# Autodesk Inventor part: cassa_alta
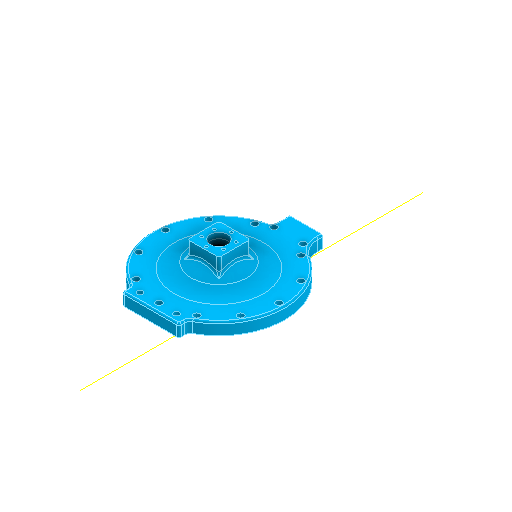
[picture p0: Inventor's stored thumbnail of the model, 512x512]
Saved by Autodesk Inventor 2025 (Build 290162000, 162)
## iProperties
Created: 2025-04
Part Number: cassa_alta
Material: Generico
Document SubType Name: Modeling
Designer: R5800u
Density: 1 g/cm^3
Appearance: Celeste medio
d120: -110,000 mm
d123: -125,000 mm
Author: R5800u
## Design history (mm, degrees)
sketch "Schizzo1"
  geometry: C1 r 80 at (0, 0); 1 further point
  constraints: 1 centre point, 1 coincident
  dimensions: "d0" = 160 diameter of C1
sketch "Schizzo2"
  geometry: L1 (0, -80)-(0, 80) reference; L2 (9, -75.641)-(-9, -75.641); A1 r 10 centre (0, -80) between (-9, -75.641) and (9, -75.641); 1 further point
  constraints: 2 end point, 2 point on circle, 1 centre point, 1 coincident, 1 horizontal
  dimensions: "d1" = 20 diameter of A1; "d11" = 18 distance of L2.end L2.start
node "Piano di lavoro1"
sketch "Schizzo3"
  geometry: L1 (0, -80)-(0, 80) reference; L2 (9, 64.412)-(-9, 64.412); A1 r 18 centre (0, 80) between (9, 64.412) and (-9, 64.412); 1 further point
  constraints: 2 end point, 2 point on circle, 1 centre point, 1 coincident, 1 perpendicular
  dimensions: "d3" = 36 diameter of A1; "d10" = 18 distance of L2.end L2.start
loft "Loft1" sketch "Schizzo3" dims "d4" = 0, "d5" = 90 deg, "d6" = 0, "d7" = 90 deg, "d8" = 0, "d9" = 90 deg
sketch "Schizzo4"
  geometry: A1 r 18 centre (0, 0) between (15.588, 9) and (15.588, -9) reference; 1 further point
sketch "Schizzo5"
  geometry: L1 (-4.359, -9)-(-4.359, 9) reference; A1 r 10 centre (0, 0) between (-4.359, -9) and (-4.359, 9) reference; 1 further point
  node "Linea chiusa proiettata1"
loft "Loft2" dims "d12" = 0, "d13" = 90 deg, "d14" = 0, "d15" = 90 deg, "d16" = 0, "d17" = 90 deg
  node "Spigoli1"
  node "Spigoli2"
sketch "Schizzo6"
  geometry: L1 (-49, -84.87)-(-32.206, -55.782) reference; L2 (-10, -121.244)-(-10, -141.244); L3 (0, 0)-(0, -170.794); A1 r 60 centre (-70, -121.244) between (-10, -121.244) and (-40, -69.282); 1 further point
  constraints: 4 end point, 2 point on circle, 2 vertical, 1 centre point, 1 point on line, 1 tangent, 3 other
  dimensions: "d18" = 20 distance of L2.start L2.end; "d66" = 10 distance between parallel lines of L3 L2
node "Piano di lavoro2"
sketch "Schizzo7"
  geometry: C1 r 18 at (0, 0); 1 further point
  constraints: 1 centre point
  dimensions: "d19" = 36 diameter of C1
loft "Loft3" sketch "Schizzo7" dims "d20" = 0, "d21" = 90 deg, "d22" = 0, "d23" = 90 deg, "d24" = 0, "d25" = 90 deg
  node "Spigoli3"
sketch "Schizzo9"
  geometry: C1 r 85.5 at (0, 0); 1 further point
  constraints: 1 centre point, 1 coincident
  dimensions: "d54" = 171 diameter of C1
extrude "Estrusione2" new body sketch "Schizzo9" stored distance "d37" = 20; taper "d38" = 0 deg
sketch "Schizzo8"
  geometry: L1 (-40.298, -107.708)-(-40.298, -141.244); L2 (-40.298, -141.244)-(19.702, -141.244); L3 (19.702, -141.244)-(19.702, -113.3); L4 (5.682, -141.244)-(8, -141.244) reference; A1 r 115 centre (0, 0) between (-40.298, -107.708) and (19.702, -113.3); 2 further points
  constraints: 6 end point, 2 perpendicular, 2 point on circle, 1 centre point, 1 coincident, 1 point on line, 1 vertical
  dimensions: "d34" = 230 diameter of A1; "d39" = 60 distance between parallel lines of L3 L1
extrude "Estrusione1" new body sketch "Schizzo8" stored distance "d35" = 50; taper "d36" = 0 deg
feature "Combina1"
  node "Solido1"
feature "Combina3"
  node "Solido3"
sketch "Schizzo10"
  geometry: L1 (0, 48.504)-(15.101, 48.504); L2 (15.101, 48.504)-(68.74, 10.012); L3 (68.74, 10.012)-(0, 10.012); L4 (0, 10.012)-(0, 48.504); L5 (68.74, 10.012)-(0, 10.012); L6 (0, 10.012)-(0, 4.744); L7 (0, 4.744)-(68.74, 4.744); L8 (68.74, 4.744)-(68.74, 10.012); 2 further points
  constraints: 16 end point, 3 parallel, 2 horizontal, 2 perpendicular
revolve "Rivoluzione1" sketch "Schizzo10" stored, may be unused: angle "d40" = 360 deg
sketch "Schizzo11"
  geometry: L1 (0, 48.504)-(15.101, 48.504) reference; L2 (15.101, 48.504)-(68.74, 10.012) reference; L3 (68.74, 10.012)-(0, 10.012) reference; L4 (0, 10.012)-(0, 48.504) reference; L5 (93.61, 2.012)-(27.101, 49.739); L6 (17.675, 56.504)-(-8, 56.504); L7 (-8, 56.504)-(-8, 2.012); L8 (-8, 2.012)-(93.61, 2.012); L9 (115, 25)-(-115, 25) reference; L10 (15.101, 48.504)-(15.101, 68.504); L11 (15.101, 68.504)-(27.101, 68.504); L12 (27.101, 68.504)-(27.101, 49.739); 5 further points
  constraints: 14 end point, 2 perpendicular, 1 vertical, 2 other
  dimensions: "d41" = 8 distance between parallel lines of L2 L5; "d69" = 20 distance of L1.end L10.end; "d70" = 12 distance of L10.end L11.end
revolve "Rivoluzione2" sketch "Schizzo11" stored, may be unused: angle "d42" = 90 deg
fillet "Raccordo1" dims "d43" = 15
fillet "Raccordo2" dims "d44" = 50
sketch "Schizzo12"
  geometry: C1 r 12.25 at (0, 0); 1 further point
  constraints: 1 centre point, 1 coincident
  dimensions: "d47" = 24.5 diameter of C1
extrude "Estrusione3" cut sketch "Schizzo12" extent not by distance; stored distance "d48" = 0; taper "d49" = 0 deg
fillet "Raccordo5" dims "d50" = 20
fillet "Raccordo11" dims "d59" = 5
fillet "Raccordo8" dims "d56" = 40
fillet "Raccordo9" dims "d57" = 10
chamfer "Smusso1" distance "d63" = 1; stored, may be unused: second distance "d64" = 2, angle "d65" = 45 deg
fillet "Raccordo14" dims "d67" = 2
fillet "Raccordo15" dims "d68" = 2
sketch "Schizzo15"
  geometry: C1 r 2.15 at (-25, 0) reference; 1 further point
extrude "Estrusione5" cut sketch "Schizzo15" distance "d81" = 25; taper "d82" = 0 deg
pattern_circular "Serie circolare2" dims angle "d84" = 360 deg
sketch "Schizzo16" dims "d86" = 210
  geometry: C1 r 12.25 at (0, 0) reference; 3 further points
  constraints: 1 coincident, 1 vertical alignment, 2 other
hole "Foro2" sketch "Schizzo16" at (0, -105) diameter "d87" = 6.4; stored, may be unused: countersink angle "d91" = 90 deg, drill point angle "d93" = 118 deg; dims "d88" = 6, "d89" = 11, "d90" = 8, "d92" = 30
sketch "Schizzo17"
  geometry: L1 (6.928, 105)-(3.464, 99); L2 (3.464, 99)-(-3.464, 99); L3 (-3.464, 99)-(-6.928, 105); L4 (-6.928, 105)-(-3.464, 111); L5 (-3.464, 111)-(3.464, 111); L6 (3.464, 111)-(6.928, 105); C1 r 1.229 at (0, 100) reference; C2 r 3.2 at (0, 105) reference; 2 further points
  constraints: 12 end point, 1 coincident, 13 other
  dimensions: "d94" = 12 distance between parallel lines of L2 L5
extrude "Estrusione6" cut sketch "Schizzo17" distance "d95" = 10; taper "d96" = 0 deg
pattern_circular "Serie circolare3" dims "d98" = 160 deg
pattern_circular "Serie circolare4" dims "d101" = 150 deg
sketch "Schizzo18"
  geometry: 3 further points
hole "Foro3" sketch "Schizzo18" at (36.774, 110.222), (-13.687, 109.855) diameter "d103" = 6.4; stored, may be unused: countersink angle "d107" = 90 deg, drill point angle "d109" = 118 deg; dims "d104" = 6, "d105" = 11, "d106" = 10, "d108" = 8
sketch "Schizzo19"
  geometry: L1 (-13.687, -116.783)-(-19.687, -113.319); L2 (-19.687, -113.319)-(-19.687, -106.391); L3 (-19.687, -106.391)-(-13.687, -102.927); L4 (-13.687, -102.927)-(-7.687, -106.391); L5 (-7.687, -106.391)-(-7.687, -113.319); L6 (-7.687, -113.319)-(-13.687, -116.783); L7 (36.774, -117.15)-(30.774, -113.686); L8 (30.774, -113.686)-(30.774, -106.758); L9 (30.774, -106.758)-(36.774, -103.293); L10 (36.774, -103.293)-(42.774, -106.758); L11 (42.774, -106.758)-(42.774, -113.686); L12 (42.774, -113.686)-(36.774, -117.15); C1 r 3.2 at (-13.687, -109.855) reference; C2 r 3.2 at (36.774, -110.222) reference; 3 further points
  constraints: 24 end point, 2 coincident, 26 other
  dimensions: "d110" = 12 distance between parallel lines of L5 L2; "d111" = 12 distance between parallel lines of L11 L8
extrude "Estrusione7" cut sketch "Schizzo19" distance "d112" = 10; taper "d113" = 0 deg
node "Piano di lavoro3"
sketch "Schizzo20"
  geometry: L1 (50, -25)-(-50, -25); L2 (-50, -25)-(-50, 25); L3 (-50, 25)-(50, 25); L4 (50, 25)-(50, -25); L5 (50, -25)-(-50, 25); L6 (-50, -25)-(50, 25); 1 further point
  constraints: 12 end point, 2 midpoint, 2 parallel, 1 horizontal, 1 perpendicular
  dimensions: "d115" = 100 distance of L2.end L3.end; "d116" = 50 distance of L1.end L2.end
extrude "Estrusione8" join sketch "Schizzo20" stored distance "d117" = 10; taper "d118" = 0 deg
fillet "Raccordo16" dims "d119" = 10
node "Piano di lavoro4"
sketch "Schizzo21"
  geometry: L1 (111.351, 191.723)-(-143.413, 191.723); L2 (-143.413, 191.723)-(-143.413, -244.583); L3 (-143.413, -244.583)-(111.351, -244.583); L4 (111.351, -244.583)-(111.351, 191.723); 1 further point
  constraints: 8 end point, 2 parallel, 1 horizontal, 1 perpendicular
extrude "Estrusione9" cut sketch "Schizzo21" extent not by distance; stored distance "d121" = 0; taper "d122" = 0 deg
node "Piano di lavoro5"
sketch "Schizzo22"
  geometry: L1 (131.776, 82.162)-(-128.363, 82.162); L2 (-128.363, 82.162)-(-128.363, -33.889); L3 (-128.363, -33.889)-(131.776, -33.889); L4 (131.776, -33.889)-(131.776, 82.162); 1 further point
  constraints: 8 end point, 2 parallel, 1 horizontal, 1 perpendicular
extrude "Estrusione10" cut sketch "Schizzo22" extent not by distance; stored distance "d124" = 0; taper "d125" = 0 deg
fillet "Raccordo17" dims "d126" = 3
sketch "Schizzo23"
  geometry: C1 r 15.101 at (0, 0) reference; C2 r 17.101 at (0, 0); C3 r 19.101 at (0, 0); 1 further point
  constraints: 2 centre point
  dimensions: "d127" = 2 radial gap between concentric circles of C1 C2; "d128" = 2 radial gap between concentric circles of C2 C3
extrude "Estrusione11" cut sketch "Schizzo23" distance "d129" = 1.5; taper "d130" = 0 deg
fillet "Raccordo18" dims "d131" = 1
sketch "Schizzo24"
  geometry: 2 further points
  dimensions: "d132" = 22 distance of point (0, 0) point (0, -22)
hole "Foro4" sketch "Schizzo24" at (0, -22) diameter "d133" = 5.3; stored, may be unused: countersink angle "d137" = 90 deg, drill point angle "d139" = 118 deg; dims "d134" = 6, "d135" = 5.5, "d136" = 2.6, "d138" = 10
pattern_circular "Serie circolare5" dims angle "d141" = 360 deg
sketch "Schizzo25"
  geometry: L1 (27.298, -25)-(3.298, -25); L2 (27.298, -25)-(27.298, -22.761); L3 (27.298, -22.761)-(27.298, -1); A1 r 24 centre (27.298, -25) between (3.298, -25) and (27.298, -1); 10 further points
  constraints: 6 end point, 5 symmetric about line, 2 coincident, 2 point on circle, 2 point on line, 1 centre point, 1 horizontal
  dimensions: "d143" = 48 diameter of A1; "d154" = 19 distance of L1.end point (9.269, -6.963); "d164" = 24 distance of L1.start point (27.298, -1)
hole "Foro5" sketch "Schizzo25" at (3.298, -25), (9.269, -6.963), (9.269, -43.037), (45.327, -43.037), (45.327, -6.963), (51.298, -25) diameter "d144" = 5.3; stored, may be unused: countersink angle "d148" = 90 deg, drill point angle "d150" = 118 deg; dims "d145" = 6, "d146" = 4, "d147" = 2, "d149" = 10
node "Asse di lavoro1"
node "Piano di lavoro6"
sketch "Schizzo27"
  geometry: L1 (-27.5, 27.5)-(27.5, 27.5); L2 (27.5, 27.5)-(27.5, -27.5); L3 (27.5, -27.5)-(-27.5, -27.5); L4 (-27.5, -27.5)-(-27.5, 27.5); L5 (-27.5, 27.5)-(27.5, -27.5); L6 (27.5, 27.5)-(-27.5, -27.5); C1 r 12.25 at (0, 0) reference; C2 r 27.101 at (0, 0) reference; 1 further point
  constraints: 12 end point, 2 midpoint, 2 parallel, 1 horizontal, 1 perpendicular
  dimensions: "d158" = 55 distance of L2.end L3.end; "d159" = 55 distance of L1.end L2.end
extrude "Estrusione13" join sketch "Schizzo27" stored distance "d160" = 10; taper "d161" = 0 deg
fillet "Raccordo19" dims "d162" = 5
fillet "Raccordo20" dims "d163" = 4
node "Modifica diretta1"
node "Piano di lavoro7"
sketch "Schizzo28"
  geometry: L1 (97.318, -11.961)-(-53.167, -11.961); L2 (-53.167, -11.961)-(-53.167, 148.805); L3 (-53.167, 148.805)-(97.318, 148.805); L4 (97.318, 148.805)-(97.318, -11.961); 1 further point
  constraints: 8 end point, 2 parallel, 1 horizontal, 1 perpendicular
extrude "Estrusione14" cut sketch "Schizzo28" extent not by distance; stored distance "d169" = 0; taper "d170" = 0 deg
sketch "Schizzo29"
  geometry: C1 r 1.6 at (23.5, -33.5) reference; C2 r 1.6 at (-1.5, -58.5) reference; C3 r 1.6 at (23.5, -83.5) reference; C4 r 1.6 at (48.5, -58.5) reference; 1 further point
  node "Riferimento3"
  node "Riferimento4"
  node "Riferimento5"
  node "Riferimento6"
sketch "Schizzo30"
  geometry: 5 further points
hole "Foro6" sketch "Schizzo30" at (-23.73, -1.419), (1.27, 23.581), (1.27, -26.419), (26.27, -1.419) diameter "d173" = 3.2; stored, may be unused: countersink angle "d177" = 90 deg, drill point angle "d179" = 118 deg; dims "d174" = 6, "d175" = 5.5, "d176" = 3.5, "d178" = 8
fillet "Raccordo21" dims "d180" = 1.4
fillet "Raccordo22" dims "d181" = 2
sketch "Schizzo31"
  geometry: C1 r 2.5 at (-7.649, -123.622) reference; C2 r 2.5 at (24.351, -123.622) reference; 1 further point
extrude "Estrusione16" cut sketch "Schizzo31" distance "d182" = 10; taper "d183" = 0 deg
sketch "Schizzo32"
  geometry: L1 (-1.5, -3.671)-(-1.5, -0.5) reference; L2 (13.649, -129.122)-(13.649, -119.21) reference; L3 (19.854, -129.122)-(13.649, -129.122) reference; L4 (43.649, -129.122)-(37.146, -129.122) reference; L5 (43.649, -124.789)-(43.649, -129.122) reference; L6 (48.5, -0.5)-(48.5, -3.671) reference; L7 (0.5, 1.5)-(46.5, 1.5) reference; C1 r 2.5 at (39.5, -5.5) reference; C2 r 2.5 at (7.5, -5.5) reference; C3 r 1.6 at (16.657, -113.428) reference; C4 r 1.6 at (41.887, -113.611) reference; C5 r 1.6 at (49.75, -103.966) reference; C6 r 1.6 at (68.966, -84.75) reference; C7 r 1.6 at (76, -58.5) reference; C8 r 1.6 at (68.966, -32.25) reference; C9 r 1.6 at (49.75, -13.034) reference; C10 r 1.6 at (5.544, -107.834) reference; C11 r 1.6 at (-17.871, -90.822) reference; C12 r 1.6 at (-28.712, -63.988) reference; C13 r 1.6 at (-23.687, -35.486) reference; C14 r 1.6 at (-4.321, -13.977) reference; C15 r 1.6 at (23.5, -6) reference; A1 r 2 centre (0.5, -0.5) between (0.5, 1.5) and (-1.5, -0.5) reference; A2 r 5 centre (-6.5, -3.671) between (-4.1, -8.057) and (-1.5, -3.671) reference; A3 r 57.5 centre (23.5, -58.5) between (-4.1, -8.057) and (9.837, -114.353) reference; A4 r 5 centre (8.649, -119.21) between (13.649, -119.21) and (9.837, -114.353) reference; A5 r 20 centre (63.649, -124.789) between (53.288, -107.683) and (43.649, -124.789) reference; A6 r 57.5 centre (23.5, -58.5) between (53.288, -107.683) and (51.1, -8.057) reference; A7 r 5 centre (53.5, -3.671) between (48.5, -3.671) and (51.1, -8.057) reference; A8 r 2 centre (46.5, -0.5) between (48.5, -0.5) and (46.5, 1.5) reference; 4 further points
  constraints: 4 other
extrude "Estrusione17" join sketch "Schizzo32" distance "d184" = 0.5; taper "d185" = 0 deg
node "Solido2"
node "Riferimento1"
node "Riferimento2"
node "Riferimento7"
node "Riferimento8"
node "Linea chiusa proiettata2"
feature "Scala1"
other parameters: "d2" = 150 deg, "d155" = -15, "d165" = 5
